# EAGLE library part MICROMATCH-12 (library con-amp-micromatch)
MicroMaTch 12 8-215464-2 / 1-215464-2 Drawing Number C-215464 DDEController.pdf
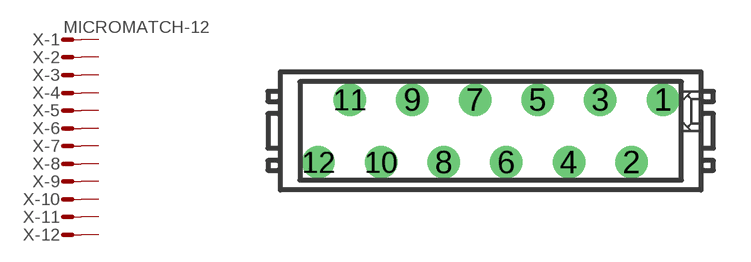
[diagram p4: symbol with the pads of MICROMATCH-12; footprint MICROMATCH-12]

Designator prefix X; gates -1=MV -2=M -3=M -4=M -5=M -6=M -7=M -8=M -9=M -10=M -11=M -12=M

## MICROMATCH-12 (MF: FARNELL; MPN: 8-215464-2; OC_FARNELL: 3784666; OC_NEWARK: 95H9857)  [MICROMATCH-12]
1  -1:S  pas
2  -2:S  pas
3  -3:S  pas
4  -4:S  pas
5  -5:S  pas
6  -6:S  pas
7  -7:S  pas
8  -8:S  pas
9  -9:S  pas
10  -10:S  pas
11  -11:S  pas
12  -12:S  pas

## Footprint MICROMATCH-12 (pad centres in mm)
MicroMaTch 12 8-215464-2 / 1-215464-2 Drawing Number C-215464 DDEController.pdf
drill 0.813 round: 1 6.985,1.27; 2 5.715,-1.27; 3 4.445,1.27; 4 3.175,-1.27; 5 1.905,1.27; 6 0.635,-1.27; 7 -0.635,1.27; 8 -1.905,-1.27; 9 -3.175,1.27; 10 -4.445,-1.27; 11 -5.715,1.27; 12 -6.985,-1.27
